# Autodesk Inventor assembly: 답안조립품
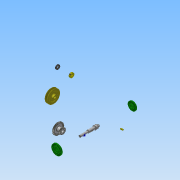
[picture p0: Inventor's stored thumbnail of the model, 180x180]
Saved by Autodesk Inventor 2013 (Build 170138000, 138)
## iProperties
Created: 2017-11
Part Number: 답안조립품
Document SubType Name: Assembly
Designer: Administrator
Author: Administrator
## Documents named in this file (14)
- C:\Users\Administrator\Desktop\471108V1016\답안조립품.iam
- C:\Users\Administrator\Desktop\471108V1016\본체.ipt
- C:\Users\Administrator\Desktop\471108V1016\V-벨트풀리.ipt
- C:\Users\Administrator\Desktop\471108V1016\뒤커버.ipt
- C:\Users\Administrator\Desktop\471108V1016\멈춤나사 - M4 x 10.ipt
- 멈춤나사 - M4 x 10.ipt
- C:\Users\Administrator\Desktop\471108V1016\베어링 6002.ipt
- C:\Users\Administrator\Desktop\471108V1016\볼트 M3 x 8.ipt
- C:\Users\Administrator\Desktop\471108V1016\스퍼기어.ipt
- C:\Users\Administrator\Desktop\471108V1016\앞커버.ipt
- C:\Users\Administrator\Desktop\471108V1016\오일 실 15 30 7.ipt
- C:\Users\Administrator\Desktop\471108V1016\축.ipt
- C:\Users\Administrator\Desktop\471108V1016\키 - 5 x 5 x 18.ipt
- C:\Users\Administrator\Desktop\471108V1016\키 - 6 x 6 x 22.ipt
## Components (1 placed, 1 different names)
1. V-벨트풀리:1
